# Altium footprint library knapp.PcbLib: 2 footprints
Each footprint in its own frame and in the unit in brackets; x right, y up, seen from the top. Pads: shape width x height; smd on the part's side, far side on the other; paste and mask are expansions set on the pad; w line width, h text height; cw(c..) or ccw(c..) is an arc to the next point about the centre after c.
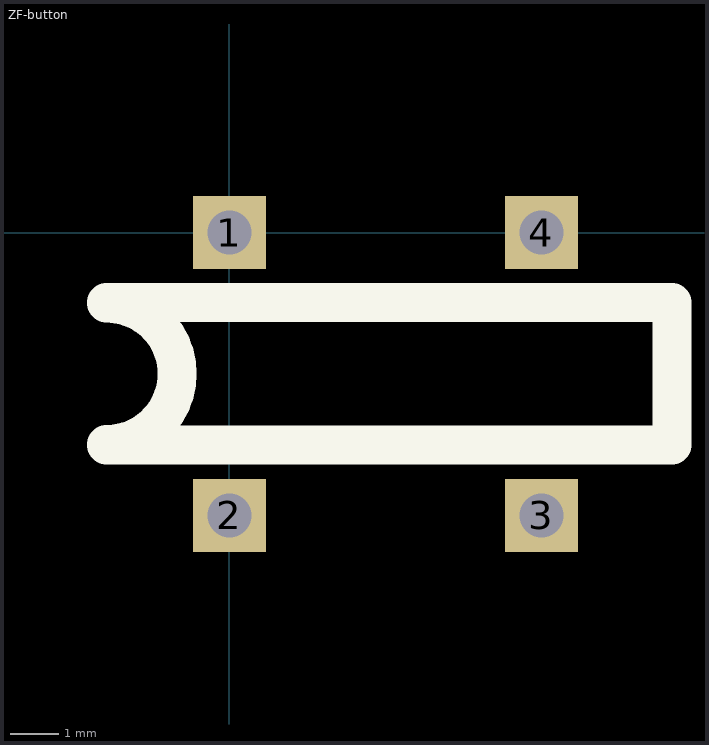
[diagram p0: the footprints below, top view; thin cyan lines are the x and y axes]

## PCBComponent_1 [mm]

## ZF-button [mm]
pads (4):
  rect 1.5x1.5 hole 0.9: 1(0,0) 2(0,-5.8) 3(6.4,-5.8) 4(6.4,0)
Top Overlay:
  lines w0.8: -2.519,-4.361 -2.519,-4.346 ccw(c-2.519,-2.896) -2.519,-1.446 -2.519,-1.431 9.081,-1.431 9.081,-4.361 -2.519,-4.361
